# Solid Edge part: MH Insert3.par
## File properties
Author: davee
Template: MH Die Plate.par
Last saved by: davee
Revision: 7
Application: Solid Edge
Accuracy: 0.990
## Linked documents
MH Die Plate.par
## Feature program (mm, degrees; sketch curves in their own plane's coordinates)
part copy "CopiedPart_1"
sketch for "Hole_1" plane through (0, 33.84, -36.2) normal (0, 0, -1) x-axis (-1, 0, 0)
  hole centre (0, 1.5) bore radius 2.4585
hole "Hole_1" finite
sketch for "ExtrudedCutout_1" plane through (0, 47.34, -33.1) normal (0, 1, 0) x-axis (-1, 0, 0)
  line (-25.9421, 11.782) -> (40.5199, 11.782)
  line (40.5199, 11.782) -> (40.5199, 17.782)
  line (40.5199, 17.782) -> (-25.9421, 17.782)
  line (-25.9421, 17.782) -> (-25.9421, 11.782)
  dimension (linear) = 25.9421
extrude "ExtrudedCutout_1" cut finite 31.75 along +normal
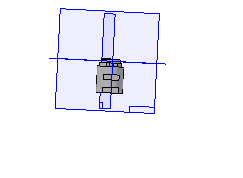
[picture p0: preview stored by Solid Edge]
